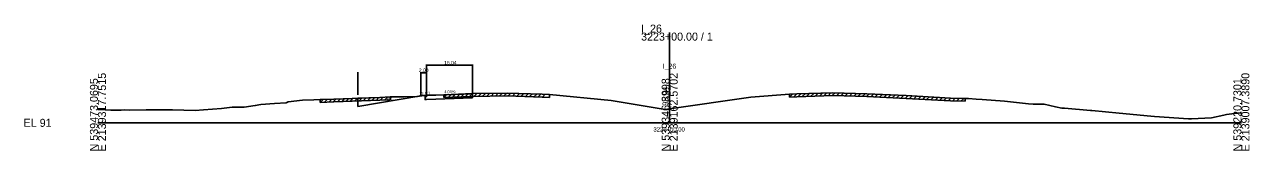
# Model space of a CAD drawing. Extents: x -13101 to 4803, y -924 to 22390.
# Drawn here: x 1974.3 to 2402.8, y 11490.3 to 11534.4 of the extents above; entities that cross this region are included whole.
import ezdxf

# ---------------------------------------------------------------- set-up
doc = ezdxf.new("R2010")
doc.units = 0
for name, color, linetype in [('RD_GPK_XS_Cell', 7, 'Continuous'), ('RD_XD_TX_Width', 7, 'Continuous'), ('RD_XS_Base', 7, 'Continuous'), ('RD_XS_EarthShd', 7, 'Continuous'), ('RD_XS_EwShp', 7, 'Continuous'), ('RD_XS_ExGround', 7, 'Continuous'), ('RD_XS_ExPaveRet', 7, 'Continuous'), ('RD_XS_OSBase', 7, 'Continuous'), ('RD_XS_Pave', 7, 'Continuous'), ('RD_XS_TieSlope', 7, 'Continuous'), ('RD_XS_TX_Baseline', 7, 'Continuous'), ('RD_XS_TX_Elev_EX', 7, 'Continuous'), ('RD_XS_TX_ShdSlope', 7, 'Continuous'), ('RD_XS_TX_Slope', 7, 'Continuous'), ('RD_XS_TX_Station', 7, 'Continuous')]:
    doc.layers.add(name, color=color, linetype=linetype)

msp = doc.modelspace()

# ---------------------------------------------------------------- linework, layer by layer
at = {"layer": 'RD_GPK_XS_Cell'}
for p, q in [((2200, 11500), (2200, 11531.57)), ((2000, 11500), (2200, 11500)), ((2200, 11500), (2400, 11500))]:
    msp.add_line(p, q, dxfattribs=at)
at = {"layer": 'RD_XD_TX_Width'}
for p, q in [((2114.96, 11520.35), (2114.96, 11509.76)), ((2114.96, 11520.15), (2131, 11520.15)), ((2131, 11520.35), (2131, 11510.4)), ((2090.96, 11517.71), (2090.96, 11509.76)), ((2112.96, 11517.71), (2112.96, 11509.6)), ((2114.96, 11517.51), (2112.96, 11517.51)), ((2114.96, 11517.71), (2114.96, 11509.76))]:
    msp.add_line(p, q, dxfattribs=at)
at = {"layer": 'RD_XS_Base'}
msp.add_line((2114.96, 11508.16), (2131, 11508.8), dxfattribs=at)
at = {"layer": 'RD_XS_EarthShd'}
msp.add_line((2114.96, 11509.56), (2112.96, 11509.4), dxfattribs=at)
at = {"layer": 'RD_XS_EwShp'}
for points in [[(2090.96, 11505.73), (2090.96, 11508.62), (2098.64, 11508.89), (2102.18, 11509.04), (2107.21, 11509.13), (2111.75, 11509.23), (2112.96, 11509.4)], [(2131, 11509.8), (2131, 11510.2), (2121.02, 11509.82), (2114.78, 11509.65), (2112.96, 11509.4), (2114.96, 11509.56), (2114.96, 11509.16), (2114.46, 11509.14), (2114.46, 11508.14), (2114.96, 11508.16), (2131, 11508.8)]]:
    msp.add_lwpolyline(points, close=True, dxfattribs=at)
at = {"layer": 'RD_XS_ExGround'}
msp.add_lwpolyline([(2000, 11504.65), (2001.06, 11504.62), (2004.54, 11504.44), (2008.08, 11504.46), (2009.42, 11504.5), (2011.06, 11504.48), (2016.9, 11504.49), (2026.11, 11504.5), (2034.06, 11504.36), (2036.92, 11504.5), (2043.17, 11505.06), (2046.93, 11505.43), (2048.98, 11505.46), (2051.11, 11505.44), (2055.03, 11506.05), (2056.94, 11506.38), (2061.8, 11506.71), (2065.84, 11506.97), (2066.55, 11507.35), (2071.5, 11507.88), (2075.5, 11508.05), (2077.77, 11508.12), (2082.53, 11508.33), (2098.64, 11508.89), (2102.18, 11509.04), (2107.21, 11509.13), (2111.75, 11509.23), (2114.78, 11509.65), (2121.02, 11509.82), (2131.1, 11510.21), (2143.14, 11510.43), (2155.45, 11510.01), (2157.97, 11509.91), (2179.58, 11507.79), (2198.41, 11504.71), (2200, 11504.94), (2228.39, 11509.02), (2241.89, 11510), (2244.53, 11510.11), (2257.06, 11510.52), (2268.93, 11510.18), (2282.68, 11509.53), (2298.2, 11508.64), (2303.38, 11508.52), (2304.5, 11508.47), (2307.17, 11508.28), (2309.33, 11508.12), (2317.18, 11507.62), (2325.56, 11506.68), (2327.19, 11506.51), (2328.17, 11506.54), (2331.03, 11506.48), (2335.02, 11505.63), (2337.2, 11505.17), (2338.14, 11505.08), (2347.21, 11504.3), (2347.65, 11504.26), (2357.26, 11503.38), (2368.3, 11502.34), (2369.56, 11502.17), (2381.49, 11501.44), (2382.17, 11501.4), (2382.58, 11501.41), (2389.57, 11501.79), (2393.82, 11502.68), (2394.83, 11502.91), (2395.75, 11503.01), (2399.57, 11503.48), (2400, 11503.54)], dxfattribs=at)
at = {"layer": 'RD_XS_ExPaveRet'}
for p, q in [((2140.52, 11509.39), (2141.54, 11510.4)), ((2142.02, 11509.41), (2143.04, 11510.43)), ((2143.52, 11509.42), (2144.49, 11510.39)), ((2252.39, 11509.37), (2253.43, 11510.4)), ((2253.89, 11509.42), (2254.93, 11510.45)), ((2255.39, 11509.47), (2256.43, 11510.5)), ((2256.89, 11509.52), (2257.88, 11510.5)), ((2258.39, 11509.48), (2259.37, 11510.46)), ((2259.89, 11509.44), (2260.87, 11510.41)), ((2077.77, 11507.12), (2078.82, 11508.17)), ((2077.77, 11507.12), (2077.77, 11508.12)), ((2077.77, 11507.12), (2082.53, 11507.33)), ((2079.27, 11507.19), (2080.32, 11508.23)), ((2080.77, 11507.25), (2081.82, 11508.3)), ((2082.27, 11507.32), (2083.31, 11508.36)), ((2082.53, 11507.33), (2098.64, 11507.89)), ((2083.77, 11507.37), (2084.81, 11508.41)), ((2085.27, 11507.43), (2086.31, 11508.46)), ((2086.77, 11507.48), (2087.81, 11508.51)), ((2088.27, 11507.53), (2089.31, 11508.57)), ((2089.77, 11507.58), (2090.81, 11508.62)), ((2091.27, 11507.63), (2092.31, 11508.67)), ((2092.77, 11507.69), (2093.81, 11508.72)), ((2094.27, 11507.74), (2095.31, 11508.77)), ((2095.77, 11507.79), (2096.81, 11508.82)), ((2097.27, 11507.84), (2098.31, 11508.88)), ((2098.64, 11507.89), (2102.18, 11508.04)), ((2098.77, 11507.89), (2099.82, 11508.94)), ((2100.27, 11507.96), (2101.32, 11509)), ((2102.18, 11509.04), (2102.18, 11508.04)), ((2121.02, 11508.82), (2122.06, 11509.86)), ((2121.02, 11508.82), (2121.02, 11509.82)), ((2121.02, 11508.82), (2131.1, 11509.21)), ((2122.52, 11508.88), (2123.56, 11509.92)), ((2124.02, 11508.94), (2125.06, 11509.97)), ((2125.52, 11508.99), (2126.56, 11510.03)), ((2127.02, 11509.05), (2128.06, 11510.09)), ((2128.52, 11509.11), (2129.56, 11510.15)), ((2130.02, 11509.16), (2131.06, 11510.2)), ((2131.1, 11509.21), (2143.14, 11509.43)), ((2131.52, 11509.21), (2132.54, 11510.23)), ((2133.02, 11509.24), (2134.04, 11510.26)), ((2134.52, 11509.27), (2135.54, 11510.29)), ((2136.02, 11509.3), (2137.04, 11510.32)), ((2137.52, 11509.33), (2138.54, 11510.35)), ((2139.02, 11509.36), (2140.04, 11510.38)), ((2143.14, 11509.43), (2155.45, 11509.01)), ((2145.02, 11509.37), (2145.99, 11510.34)), ((2146.52, 11509.32), (2147.49, 11510.29)), ((2148.02, 11509.27), (2148.99, 11510.23)), ((2149.52, 11509.22), (2150.49, 11510.18)), ((2151.02, 11509.16), (2151.99, 11510.13)), ((2152.52, 11509.11), (2153.49, 11510.08)), ((2154.02, 11509.06), (2154.99, 11510.03)), ((2155.45, 11509.01), (2157.97, 11508.91)), ((2155.52, 11509.01), (2156.49, 11509.97)), ((2157.97, 11509.91), (2157.97, 11508.91)), ((2241.89, 11509), (2242.94, 11510.04)), ((2241.89, 11509), (2241.89, 11510)), ((2241.89, 11509), (2244.53, 11509.11)), ((2243.39, 11509.06), (2244.44, 11510.1)), ((2244.53, 11509.11), (2257.06, 11509.52)), ((2244.89, 11509.12), (2245.93, 11510.15)), ((2246.39, 11509.17), (2247.43, 11510.2)), ((2247.89, 11509.22), (2248.93, 11510.25)), ((2249.39, 11509.27), (2250.43, 11510.3)), ((2250.89, 11509.32), (2251.93, 11510.35)), ((2257.06, 11509.52), (2268.93, 11509.18)), ((2261.39, 11509.4), (2262.37, 11510.37)), ((2262.89, 11509.35), (2263.87, 11510.33)), ((2264.39, 11509.31), (2265.37, 11510.28)), ((2265.89, 11509.27), (2266.87, 11510.24)), ((2267.39, 11509.22), (2268.37, 11510.2)), ((2268.89, 11509.18), (2269.85, 11510.14)), ((2268.93, 11509.18), (2282.68, 11508.53)), ((2270.39, 11509.11), (2271.35, 11510.07)), ((2271.89, 11509.04), (2272.85, 11509.99)), ((2273.39, 11508.97), (2274.35, 11509.92)), ((2274.89, 11508.9), (2275.85, 11509.85)), ((2276.39, 11508.83), (2277.35, 11509.78)), ((2277.89, 11508.76), (2278.85, 11509.71)), ((2279.39, 11508.69), (2280.35, 11509.64)), ((2280.89, 11508.62), (2281.85, 11509.57)), ((2282.39, 11508.55), (2283.34, 11509.49)), ((2282.68, 11508.53), (2298.2, 11507.64)), ((2283.89, 11508.46), (2284.84, 11509.41)), ((2285.39, 11508.38), (2286.34, 11509.32)), ((2286.89, 11508.29), (2287.84, 11509.23)), ((2288.39, 11508.2), (2289.34, 11509.15)), ((2289.89, 11508.12), (2290.84, 11509.06)), ((2291.39, 11508.03), (2292.34, 11508.97)), ((2292.89, 11507.94), (2293.84, 11508.89)), ((2294.39, 11507.86), (2295.34, 11508.8)), ((2295.89, 11507.77), (2296.84, 11508.71)), ((2297.39, 11507.68), (2298.35, 11508.63)), ((2298.2, 11507.64), (2303.38, 11507.52)), ((2298.89, 11507.62), (2299.87, 11508.6)), ((2300.39, 11507.59), (2301.37, 11508.57)), ((2301.89, 11507.55), (2302.87, 11508.53)), ((2303.38, 11508.52), (2303.38, 11507.52))]:
    msp.add_line(p, q, dxfattribs=at)
at = {"layer": 'RD_XS_OSBase'}
for p, q in [((2114.46, 11509.14), (2114.96, 11509.16)), ((2114.46, 11508.14), (2114.46, 11509.14)), ((2114.96, 11508.16), (2114.46, 11508.14)), ((2114.96, 11509.16), (2114.96, 11509.56)), ((2131, 11509.8), (2131, 11510.2)), ((2131, 11508.8), (2131, 11509.8))]:
    msp.add_line(p, q, dxfattribs=at)
at = {"layer": 'RD_XS_Pave'}
msp.add_line((2114.96, 11509.56), (2131, 11510.2), dxfattribs=at)
at = {"layer": 'RD_XS_TieSlope'}
for p, q in [((2112.96, 11509.4), (2090.96, 11505.73)), ((2090.96, 11505.73), (2090.96, 11508.62))]:
    msp.add_line(p, q, dxfattribs=at)

# ---------------------------------------------------------------- texts
at = {"layer": 'RD_GPK_XS_Cell'}
for s, p in [('I_26', (2190, 11531.57)), ('3223+00.00 / 1', (2190, 11528.77)), ('EL 91', (1974, 11498.6))]:
    msp.add_text(s, height=2.8, dxfattribs=at).set_placement(p)
for s, p in [('N 539473.0695', (2000, 11490)), ('E 2139317.7515', (2002.8, 11490)), ('N 539346.8998', (2200, 11490)), ('E 2139162.5702', (2202.8, 11490)), ('N 539220.7301', (2400, 11490)), ('E 2139007.3890', (2402.8, 11490))]:
    msp.add_text(s, height=2.8, rotation=90, dxfattribs=at).set_placement(p)
at = {"layer": 'RD_XD_TX_Width'}
for s, p in [('2.00', (2112.27, 11517.76)), ('16.04', (2121.13, 11520.4))]:
    msp.add_text(s, height=1.25, dxfattribs=at).set_placement(p)
at = {"layer": 'RD_XS_TX_Baseline'}
msp.add_text('I_26', height=1.75, dxfattribs=at).set_placement((2197.6, 11518.94))
at = {"layer": 'RD_XS_TX_Elev_EX'}
msp.add_text('95.94', height=2, rotation=90, dxfattribs=at).set_placement((2199.5, 11505.94))
at = {"layer": 'RD_XS_TX_ShdSlope'}
msp.add_text('12.5:1', height=1, rotation=4.5739, dxfattribs=at).set_placement((2112.43, 11509.6))
msp.add_text('12.5:1', height=1, rotation=4.5739, dxfattribs=at).set_placement((2112.43, 11509.6))
at = {"layer": 'RD_XS_TX_Slope'}
for s, rotation, p in [('4.00%', 2.2906, (2121.16, 11510.3)), ('6:1', 9.4623, (2101.23, 11507.69))]:
    msp.add_text(s, height=1, rotation=rotation, dxfattribs=at).set_placement(p)
at = {"layer": 'RD_XS_TX_Station'}
msp.add_text('3223+00.00', height=1.5, dxfattribs=at).set_placement((2194.32, 11496.94))

doc.saveas('drawing.dxf')
